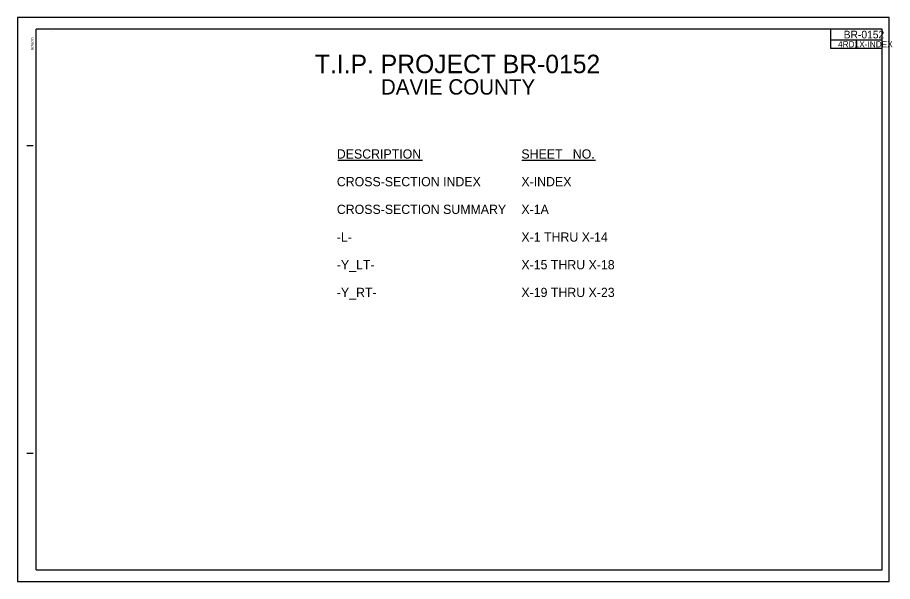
# Model space of a CAD drawing. Extents: x 1552903 to 1553045, y 811348 to 811440.
import ezdxf

# ---------------------------------------------------------------- set-up
doc = ezdxf.new("R2010")
doc.units = 0
for name, color, linetype in [('Exist DTM Crownline', 7, 'Continuous'), ('Exist Property Monument CELL', 7, 'Continuous'), ('Exist Structure Major Bridge WW', 7, 'Continuous'), ('Exist Structure Minor Catch Basin', 7, 'Continuous')]:
    doc.layers.add(name, color=color, linetype=linetype)

msp = doc.modelspace()

# ---------------------------------------------------------------- linework, layer by layer
at = {"layer": 'Exist DTM Crownline'}
for p, q in [((1552906.19, 811350.21), (1552906.19, 811438.12)), ((1553043.69, 811438.12), (1552906.19, 811438.12)), ((1552908.69, 811437.71), (1552908.69, 811437.71)), ((1553035.36, 811434.96), (1553035.36, 811438.12)), ((1553043.69, 811350.21), (1553043.69, 811438.12)), ((1553043.69, 811436.34), (1553035.36, 811436.34)), ((1553039.52, 811434.96), (1553039.52, 811436.34)), ((1553043.69, 811434.96), (1553035.36, 811434.96)), ((1552904.65, 811419.17), (1552905.69, 811419.17)), ((1552904.65, 811369.17), (1552905.69, 811369.17)), ((1552906.19, 811350.21), (1553043.69, 811350.21)), ((1552908.69, 811350.21), (1552908.69, 811350.21))]:
    msp.add_line(p, q, dxfattribs=at)
at = {"layer": 'Exist Property Monument CELL'}
for p, q in [((1553044.82, 811440), (1552903.15, 811440)), ((1552903.15, 811440), (1552903.15, 811348.33)), ((1553044.82, 811348.33), (1553044.82, 811440)), ((1552903.15, 811348.33), (1553044.82, 811348.33))]:
    msp.add_line(p, q, dxfattribs=at)
at = {"layer": 'Exist Structure Major Bridge WW'}
for p, q in [((1552955.21, 811416.8), (1552968.96, 811416.8)), ((1552985.16, 811416.8), (1552997.1, 811416.8))]:
    msp.add_line(p, q, dxfattribs=at)

# ---------------------------------------------------------------- texts
at = {"layer": 'Exist DTM Crownline'}
msp.add_text('5/26/20', height=0.437, rotation=90, dxfattribs=at).set_placement((1552905.8, 811434.73))
at = {"layer": 'Exist Structure Major Bridge WW'}
for s, height, p in [('T.I.P. PROJECT BR-0152', 3, (1552951.5, 811430.95)), ('DAVIE COUNTY', 2.5, (1552962.23, 811427.47)), ('DESCRIPTION', 1.5, (1552955.06, 811417.07)), ('SHEET   NO.', 1.5, (1552985.06, 811417.07)), ('CROSS-SECTION INDEX', 1.5, (1552955.06, 811412.57)), ('X-INDEX', 1.5, (1552985.06, 811412.57)), ('CROSS-SECTION SUMMARY', 1.5, (1552955.06, 811408.07)), ('X-1A', 1.5, (1552985.06, 811408.07)), ('-L-                      ', 1.5, (1552955.06, 811403.57)), ('X-1 THRU X-14', 1.5, (1552985.06, 811403.57)), ('X-15 THRU X-18', 1.5, (1552985.06, 811399.07)), ('-Y_LT-           ', 1.5, (1552955.06, 811399.07)), ('-Y_RT-           ', 1.5, (1552955.06, 811394.57)), ('X-19 THRU X-23', 1.5, (1552985.06, 811394.57))]:
    msp.add_text(s, height=height, dxfattribs=at).set_placement(p)
at = {"layer": 'Exist Structure Minor Catch Basin'}
for s, height, p in [('BR-0152', 1.25, (1553037.45, 811436.6)), ('4RD1', 1, (1553036.54, 811435.15)), ('X-INDEX', 1, (1553039.99, 811435.15))]:
    msp.add_text(s, height=height, dxfattribs=at).set_placement(p)

doc.saveas('drawing.dxf')
